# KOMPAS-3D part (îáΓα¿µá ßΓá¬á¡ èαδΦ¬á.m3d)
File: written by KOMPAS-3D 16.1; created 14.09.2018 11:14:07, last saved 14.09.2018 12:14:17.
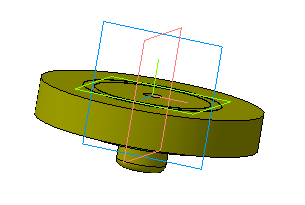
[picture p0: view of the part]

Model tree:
1. Эскиз:1
2. Операция вращения:2
     Угол 1 = 360
3. Эскиз:2
4. Вырезать элемент выдавливания:1
     Расстояние 1 = 30
5. Эскиз:3
6. Операция выдавливания:1
     Расстояние 1 = 12
7. Скругление:1
     Радиус = 3
8. Эскиз:4
9. Вырезать элемент выдавливания:2  (labels: Полипропилен  ГОСТ 26996-86)
     Толщина стенки 1 = 0.1; Расстояние 1 = 0.1

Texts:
  Линейный размер с обрывом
